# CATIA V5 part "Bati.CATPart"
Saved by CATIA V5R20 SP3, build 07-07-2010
Part number: Bati
Bounding box of the stored display mesh (mm): x -22 to 9, y -7 to 71, z -5 to 16
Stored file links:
  C:\Documents and Settings\Propriétaire\Mes documents\IFMA\COURS\PROJ IAO\CATIA\Bati.CATPart
  C:\Documents and Settings\Propriétaire\Mes documents\IFMA\COURS\PROJ IAO\CATIA\dwalter.CATProduct
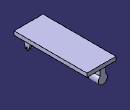
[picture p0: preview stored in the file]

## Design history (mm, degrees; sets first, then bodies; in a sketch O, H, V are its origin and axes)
Set1
  Plane1 to Plane3: linked copy from another document
  Point1: linked copy from another document
  Point2: linked copy from another document
  Line1: linked copy from another document
  Plane4: linked copy from another document
  Line2: linked copy from another document
  Line3: linked copy from another document
Body1 (main body)
  Sketch1 on Plane1, origin (0, 0, 0), H (0, 1, 0), V (0, 0, 1)
    arc A1 centre (0, 0) radius 2 from (-1.9365, -0.5) to (1.9365, -0.5) ccw
    point P1 (0, 0)
    point P2 (-1.9365, -0.5)
    point P3 (1.9365, -0.5)
    circle A2 centre (0, 0) radius 1
    point P4 (0, 0)
    line L1 (-1.9365, -0.5) -> (-5.164, 12)
    line L2 (5.164, 12) -> (-5.164, 12)
    line L3 (1.9365, -0.5) -> (5.164, 12)
    radius A1 = 2
    radius A2 = 1
    distance P3 H = 0.5
    distance H L2 = 12
    coincidence: O P1, P4 P1
    symmetry: P2 P3 V, L3 L1 V
    horizontal: L2 H
    tangency: L3 A1
  Pad1: profile Sketch1, direction (1, 0, 0), length 2
  Sketch2 on Plane2, origin (-3, 0, 0), H (0, 1, 0), V (0, 0, 1)
    projected arc E1 centre (0, 0) radius 2 from (-1.9365, -0.5) to (1.9365, -0.5) ccw from edge [face of Pad1 from Sketch1.A1 | end face of Pad1]
    projected line E2 (1.9365, -0.5) -> (5.164, 12) from edge [face of Pad1 from Sketch1.L3 | end face of Pad1]
    projected line E3 (5.164, 12) -> (-5.164, 12) from edge [face of Pad1 from Sketch1.L2 | end face of Pad1]
    projected line E4 (-5.164, 12) -> (-1.9365, -0.5) from edge [face of Pad1 from Sketch1.L1 | end face of Pad1]
    projected circle E5 centre (0, 0) radius 1 from edge [end face of Pad1 | face of Pad1 from Sketch1.A2]
  Pad2: profile Sketch2, direction (-1, 0, 0), length 2
  Sketch3 on Plane3, origin (-10, 0, 0), H (0, 1, 0), V (0, 0, 1)
    point P1 (23, 0)
    point P2 (58, 0)
    line L1 (58, 0) -> (58, 5)
    line L2 (58, 5) -> (69, 5)
    line L3 (23, 0) -> (23, 5)
    line L4 (23, 5) -> (12, 5)
    point P7 (58, 0)
    line L5 (58, 0) -> (69, 0)
    line L6 (69, 0) -> (69, 5)
    point P9 (23, 0)
    line L7 (23, 0) -> (12, 0)
    line L8 (12, 0) -> (12, 5)
    reference projected line E2 (58, 0) -> (30, 0) from Line1
    length L8 = 5
    distance L8 L3 = 11
    distance L6 L1 = 11
    distance L8 V = 12
    distance L1 V = 58
    vertical: L1 V, L3 V, L6 V, L8 V
    horizontal: L2 H, L4 H, L5 H, L7 H
    coincidence: L4 L2, L5 L7, P7 P2, L5 E2, P1 P9
  Shaft1: profile Sketch3, axis Line1, angle 360
  Sketch4 on face of Pad2 from Sketch2.E3, origin (0, 0, 12), H (1, 0, 0), V (0, 1, 0)
    line L1 (-22, 71) -> (9, 71)
    line L2 (9, 71) -> (9, -7)
    line L3 (9, -7) -> (-22, -7)
    line L4 (-22, -7) -> (-22, 71)
    length L2 = 78
    length L3 = 31
    distance V L2 = 9
    distance H L3 = 7
    horizontal: L1 H, L3 H
    vertical: L2 V, L4 V
  Pad3: profile Sketch4, direction (0, 0, 1), length 4
  Sketch5 on start face of Pad3, origin (0, 0, 12), H (1, 0, 0), V (0, -1, 0)
    reference projected line E1 (-15, -12) -> (-5, -12) from edge [face of Shaft1 from Sketch3.L4 | face of Shaft1 from Sketch3.L8]
    reference projected line E2 (-15, -23) -> (-5, -23) from edge [face of Shaft1 from Sketch3.L3 | face of Shaft1 from Sketch3.L4]
    point P5 (-13, -12)
    line L1 (-13, -12) -> (-7, -12)
    line L2 (-7, -12) -> (-7, -23)
    line L3 (-7, -23) -> (-13, -23)
    line L4 (-13, -23) -> (-13, -12)
    point P7 (-7, -23)
    point P9 (-9, -70)
    reference projected line E3 (-10, -58) -> (-10, -30) from Line1
    length L1 = 6
    coincidence: P5 E1, P7 E2
    horizontal: L1 H, L3 H
    vertical: L2 V, L4 V
    symmetry: L2 L4 E3
  Pad4: profile Sketch5, direction (0, 0, -1), up to face of Shaft1 from Sketch3.L4
  Sketch6 on start face of Pad3, origin (0, 0, 12), H (1, 0, 0), V (0, -1, 0)
    reference projected line E2 (-13, -12) -> (-13, -23) from edge [start face of Pad3 | face of Pad4 from Sketch5.L4]
    reference projected line E3 (-7, -23) -> (-7, -12) from edge [start face of Pad3 | face of Pad4 from Sketch5.L2]
    reference projected line E5 (-15, -58) -> (-5, -58) from edge [face of Shaft1 from Sketch3.L2 | face of Shaft1 from Sketch3.L1]
    reference projected line E6 (-15, -69) -> (-5, -69) from edge [face of Shaft1 from Sketch3.L6 | face of Shaft1 from Sketch3.L2]
    line L1 (-13, -58) -> (-7, -58)
    line L2 (-7, -58) -> (-7, -69)
    line L3 (-7, -69) -> (-13, -69)
    line L4 (-13, -69) -> (-13, -58)
    horizontal: L1 H, L3 H
    vertical: L2 V, L4 V
    coincidence: L1 E5, L3 E6, L2 E3, L4 E2
  Pad5: profile Sketch6, direction (0, 0, -1), up to face of Shaft1 from Sketch3.L2
  Sketch7 on Plane4, origin (0, 44, 0), H (1, 0, 0), V (0, 0, 1)
    line L1 (-12, 2) -> (-8, 2)
    line L2 (-8, 2) -> (-8, -2)
    line L3 (-8, -2) -> (-12, -2)
    line L4 (-12, -2) -> (-12, 2)
    reference projected line E1 (-10, 0) -> (10, 0) from Line2
    reference projected line E2 (-10, 10) -> (-10, -10) from Line3
    length L2 = 4
    length L1 = 4
    horizontal: L1 H, L3 H
    vertical: L2 V, L4 V
    symmetry: L1 L3 E1, L2 L4 E2
  Pocket1: profile Sketch7, direction (0, 1, 0), length 21
  Pocket2: profile Sketch7, direction (0, -1, 0), length 28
